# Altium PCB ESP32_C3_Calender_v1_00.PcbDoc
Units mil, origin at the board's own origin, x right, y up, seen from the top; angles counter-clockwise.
Board outline 2500 x 1692.91 mil, 2 copper layers (Top Layer, Bottom Layer), stack 65.792 mil thick; 16 components, 17 nets, 85 pads, 115 vias.
Unrouted connection lines stored in the file: 42.
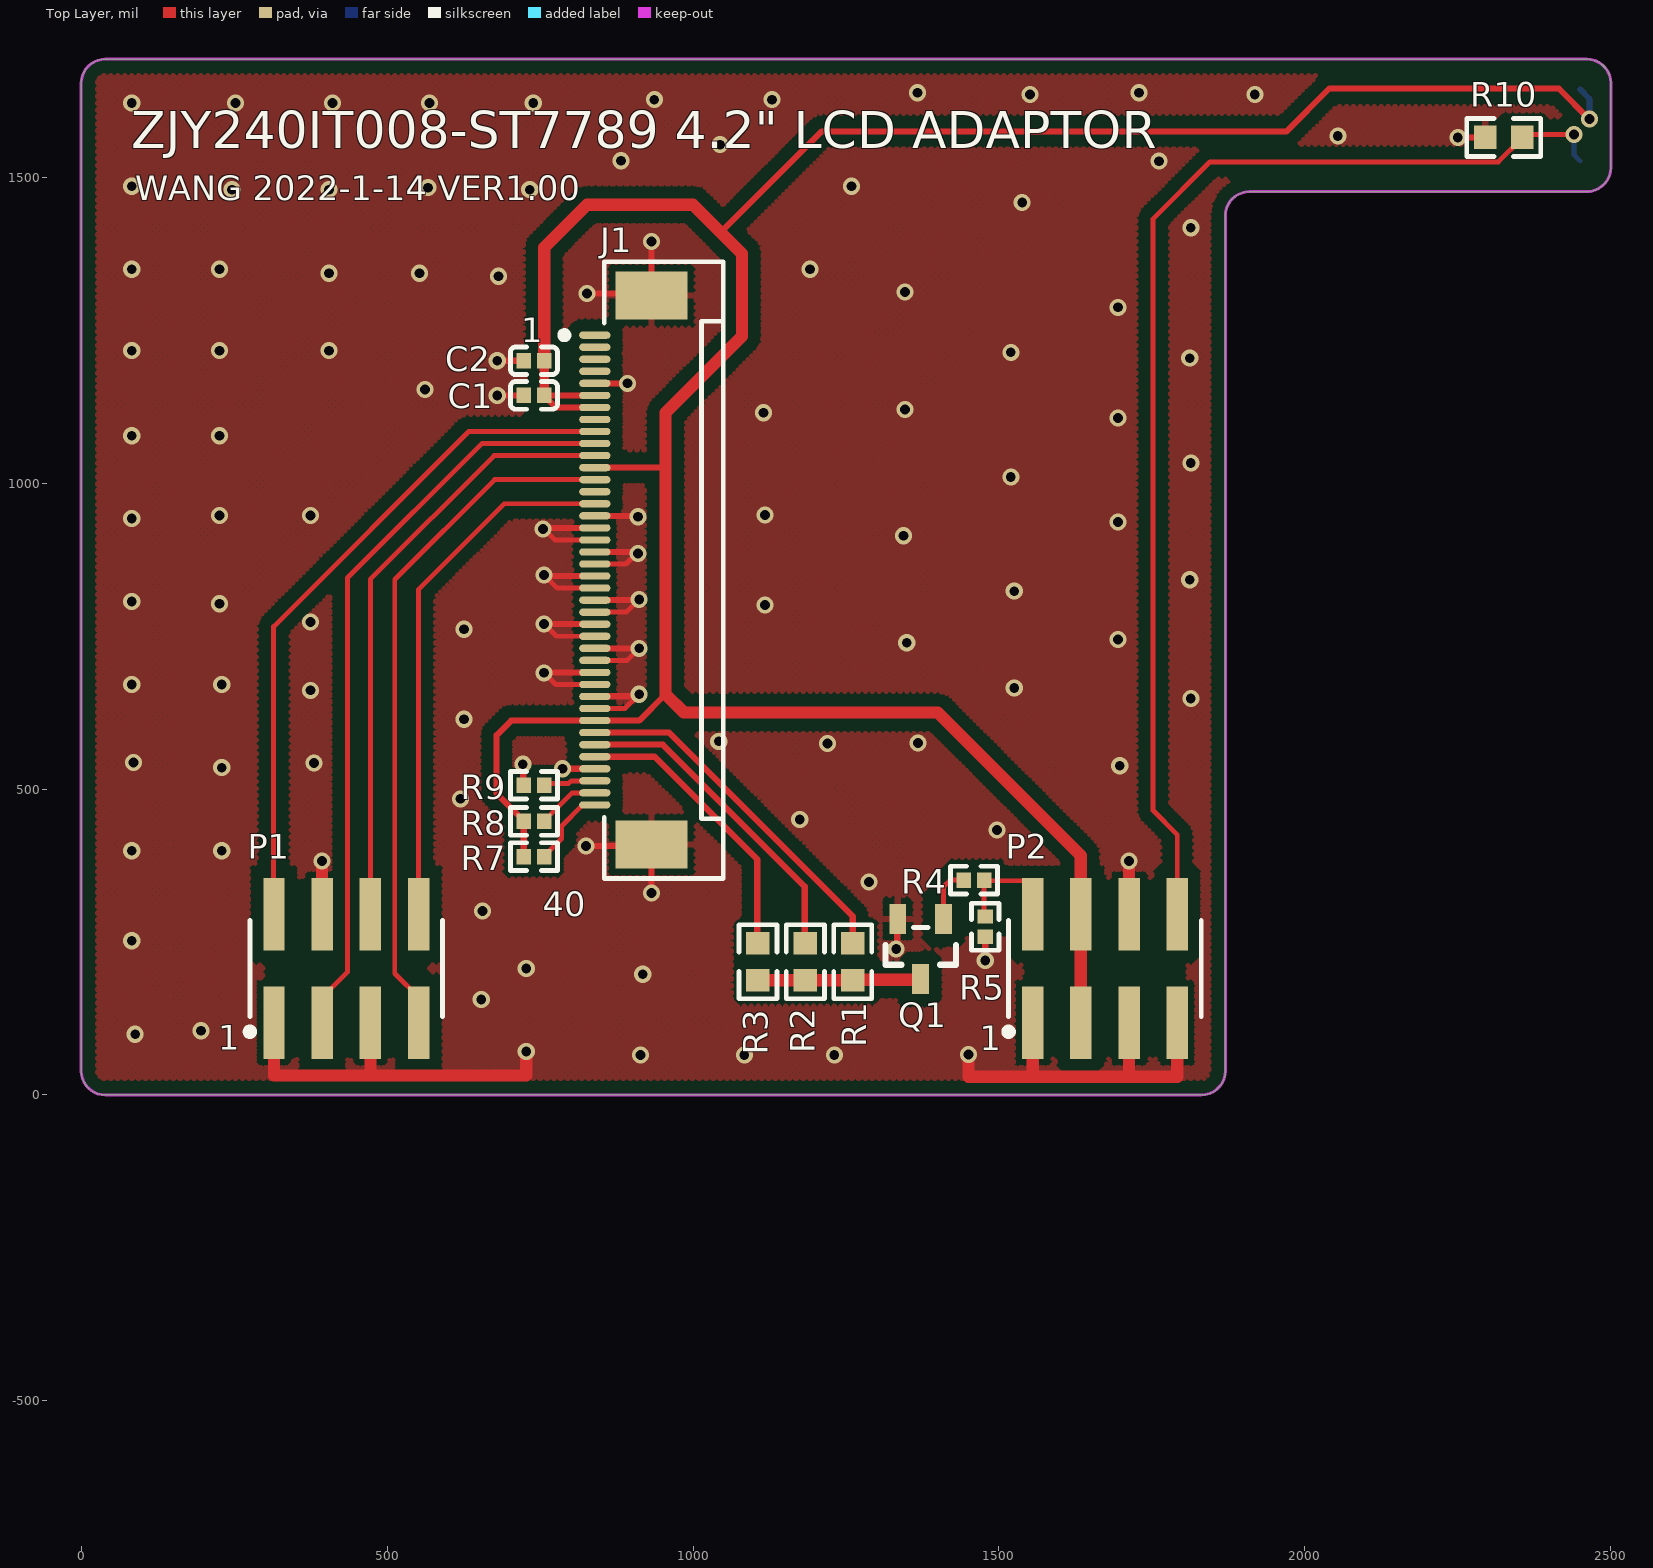
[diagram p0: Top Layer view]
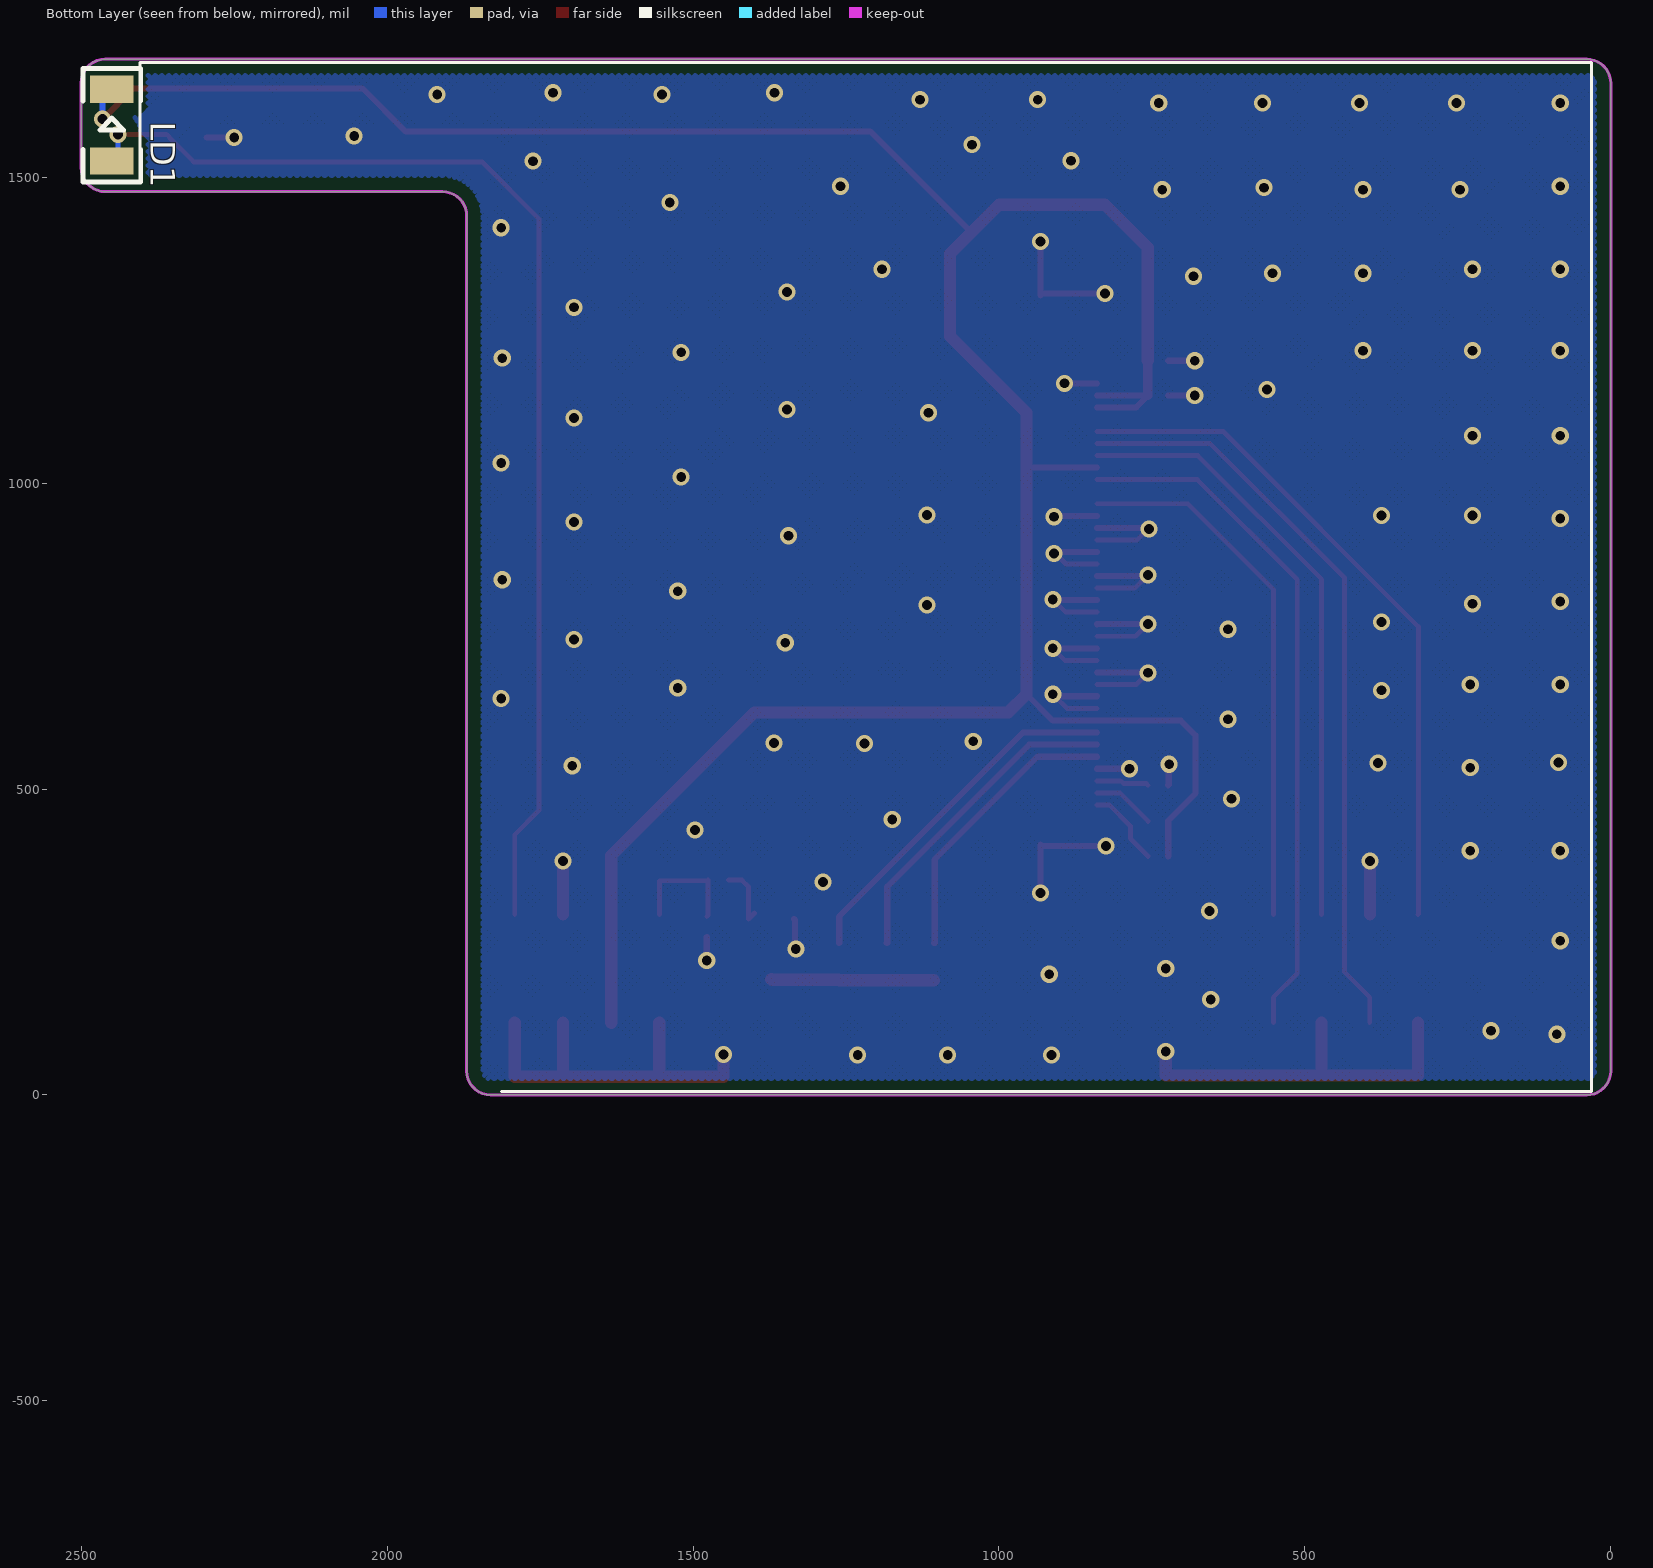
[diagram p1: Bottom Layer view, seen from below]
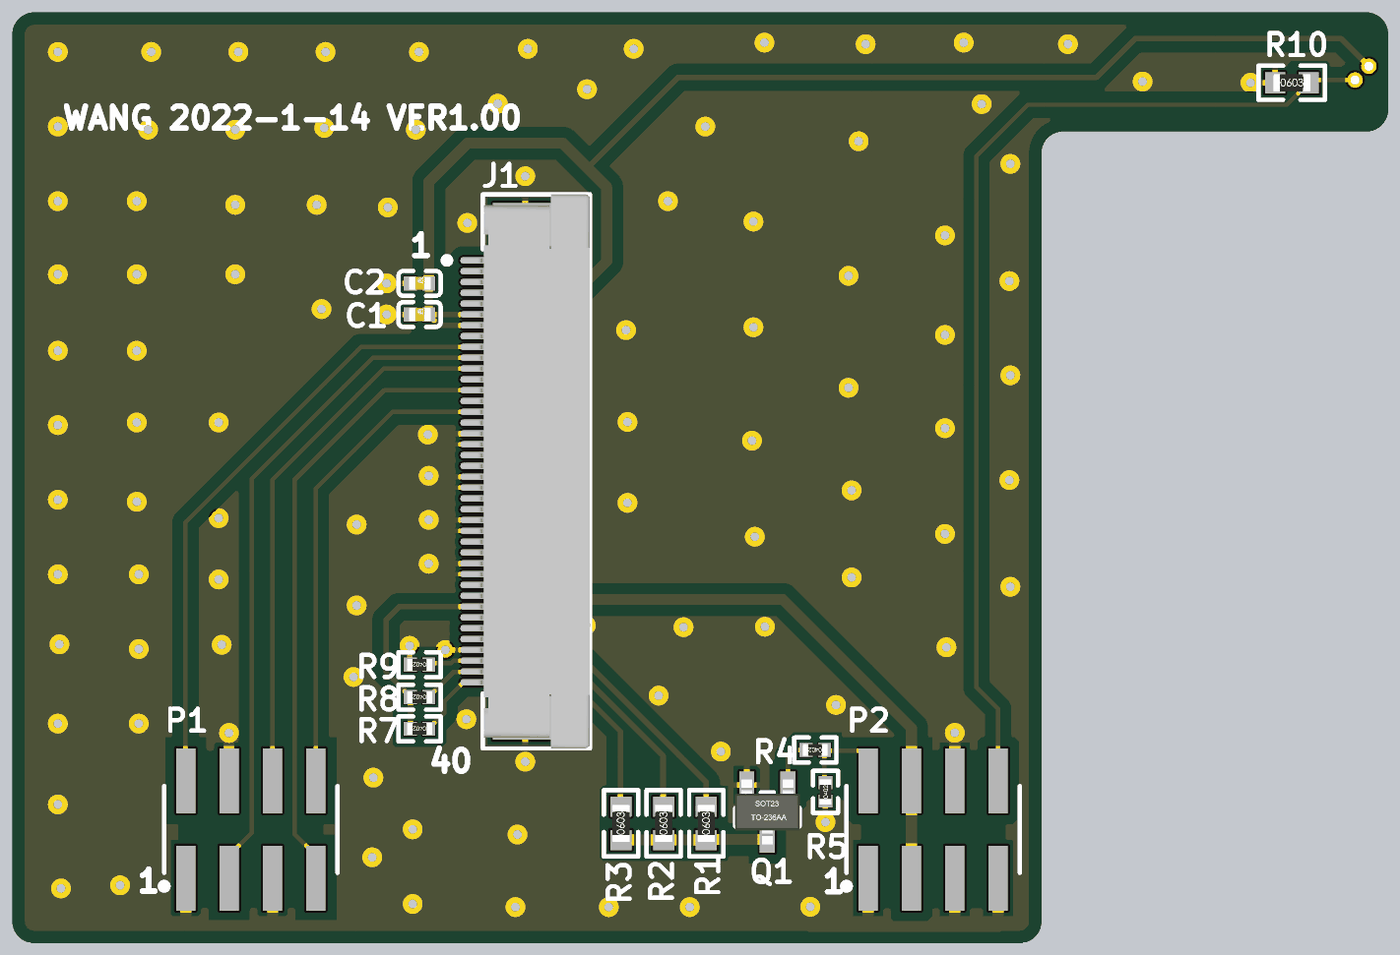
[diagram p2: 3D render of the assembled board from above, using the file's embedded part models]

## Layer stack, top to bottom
Top Solder: solder mask 0.4, Solder Resist, Dk 3.5
Top Layer: signal copper 1.4
Dielectric 1: dielectric 62.9921, FR-4, Dk 4.8
Bottom Layer: signal copper 1.4
Bottom Solder: solder mask 0.4, Solder Resist, Dk 3.5

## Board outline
0,39.37 ccw(c39.37,39.37) 39.37,0 1830.71,0 ccw(c1830.71,39.37) 1870.08,39.37 1870.08,1437.01 cw(c1909.45,1437.01) 1909.45,1476.38 2460.63,1476.38 ccw(c2460.63,1515.75) 2500,1515.75 2500,1653.54 ccw(c2460.63,1653.54) 2460.63,1692.91 39.37,1692.91 ccw(c39.37,1653.54) 0,1653.54

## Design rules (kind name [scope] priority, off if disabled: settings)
Clearance Clearance_3 [InNamedPolygon('GND_L02_P006') Or  InNamedPolygon('GND_L01_P004')] p1: gap=20 ignorepadtopadclearanceinfootprint=FALSE
Clearance Clearance_2 [InNamedPolygon('GND_L02_P006') Or  InNamedPolygon('GND_L01_P004')] p2: gap=10 ignorepadtopadclearanceinfootprint=FALSE except(0: Arc-Hole Track-Hole SMDPad-Hole THPad-Hole Via-Hole Fill-Hole Poly-Hole Region-Hole Text-Hole)
Clearance Clearance_1 [InNamedPolygon('GND_L01_P000') Or  InNamedPolygon('GND_BOTTOM')] p3: gap=15 ignorepadtopadclearanceinfootprint=FALSE
Clearance [All] p4: gap=6 ignorepadtopadclearanceinfootprint=FALSE
ComponentClearance [All] p1: gap=2 collisioncheckmode=3 verticalgap=0 showdistances=FALSE
HoleSize [All] p1: absolutevalues=TRUE maxlimit=200 minlimit=1 maxpercent=80.000 minpercent=20.000
MinimumSolderMaskSliver [All] p1: minsoldermaskwidth=0
PolygonConnect PolygonConnect_2 [InNet('GND') vs IsThruPin] p1: connectstyle=Direct reliefconductorwidth=10 reliefentries=4 polygonreliefangle="90 Angle" airgapwidth=10
PolygonConnect PolygonConnect_1 [IsVia] p2: connectstyle=Direct reliefconductorwidth=10 reliefentries=4 polygonreliefangle="90 Angle" airgapwidth=10
PolygonConnect [All] p3: connectstyle=Relief reliefconductorwidth=10 reliefentries=4 polygonreliefangle="90 Angle" airgapwidth=10
RoutingVias [All] p1: holewidth=16 width=28 viastyle="Through Hole" minholewidth=16 minwidth=28 maxholewidth=28 maxwidth=50
SilkToSilkClearance [All] p1: silktosilkclearance=0
SilkToSolderMaskClearance [IsPad] p1: minsilkscreentomaskgap=0 clearancetoexposedcopper=TRUE
SolderMaskExpansion [All] p1: expansion=4
Width [All] p1: maxlimit=30 minlimit=8 preferedwidth=10
25 further rules are at their usual default settings.

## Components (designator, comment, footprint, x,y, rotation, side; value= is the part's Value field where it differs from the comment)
C1 "4.7uF (475) 20% 10V" LC-0402_C 740,1143.43 r0 top
C2 "100nF (104) 10% 16V" LC-0402_C 740,1200 r0 top
J1 "FPC40 Socket" FPC40-P0.5-2 876.25,858 r90 top locked
LD1 "PTSMD026" LC-1206_DIODE 2450,1585 r90 bottom
P1 "Header 4X2" HDR2X4-P2-SMD 433.3,206.69 r0 top locked
P2 "Header 4X2" HDR2X4-P2-SMD 1673.23,206.69 r0 top locked
Q1 "SS8050 Y1" LC-SOT-23(SOT-23-3) 1372,238.49 r90 top
R1 "33Ω (33R0) ±1%" LC-0603_R 1261,217.81 r90 top
R2 "33Ω (33R0) ±1%" LC-0603_R 1183.5,217.81 r90 top
R3 "33Ω (33R0) ±1%" LC-0603_R 1106,217.81 r90 top
R4 "1KΩ (1001) ±1%" LC-0402_R 1459,351.16 r180 top
R5 "4.7KΩ (4701) ±1%" LC-0402_R 1477.57,275 r90 top
R7 "4.7KΩ (4701) ±1%" LC-0402_R 740,389.61 r180 top
R8 "4.7KΩ (4701) ±1%" LC-0402_R 740,447.24 r180 top
R9 "4.7KΩ (4701) ±1%" LC-0402_R 740,506.3 r180 top
R10 "3.9KΩ (3901) ±1%" LC-0603_R 2325,1565 r0 top

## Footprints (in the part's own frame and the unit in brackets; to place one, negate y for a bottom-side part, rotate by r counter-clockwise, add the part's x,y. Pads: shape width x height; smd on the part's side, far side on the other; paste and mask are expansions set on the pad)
FPC40-P0.5-2 [mm] "X05B20U40T"
  oval 0.3x1.3 smd: 1(9.75,0.934) 2(9.25,0.934) 3(8.75,0.934) 4(8.25,0.934) 5(7.75,0.934) 6(7.25,0.934) 7(6.75,0.934) 8(6.25,0.934) 9(5.75,0.934) 10(5.25,0.934) 11(4.75,0.934) 12(4.25,0.934) 13(3.75,0.934) 14(3.25,0.934) 15(2.75,0.934) 16(2.25,0.934) 17(1.75,0.934) 18(1.25,0.934) 19(0.75,0.934) 20(0.25,0.934) 21(-0.25,0.934) 22(-0.75,0.934) 23(-1.25,0.934) 24(-1.75,0.934) 25(-2.25,0.934) 26(-2.75,0.934) 27(-3.25,0.934) 28(-3.75,0.934) 29(-4.25,0.934) 30(-4.75,0.934) 31(-5.25,0.934) 32(-5.75,0.934) 33(-6.25,0.934) 34(-6.75,0.934) 35(-7.25,0.934) 36(-7.75,0.934) 37(-8.25,0.934) 38(-8.75,0.934) 39(-9.25,0.934) 40(-9.75,0.934)
  rect 2x3 smd: BK1(-11.4,-1.416) BK2(11.4,-1.416)
  silkscreen extent -12.8,-4.4 12.8,2.34, body extent -12.8,-4.4 12.8,1.57, height 2
HDR2X4-P2-SMD [mm]
  rect 0.89x3 smd: 1(-3,-2.25) 2(-3,2.25) 3(-1,-2.25) 4(-1,2.25) 5(1,-2.25) 6(1,2.25) 7(3,-2.25) 8(3,2.25)
  silkscreen extent -4.15,-2.77 4,2, body extent -4,-3.2 4,3.2, height 7.1
LC-0402_C [mm]
  rect 0.6x0.65 smd mask+0.051: 1(-0.425,0) 2(0.425,0)
  silkscreen extent -0.97,-0.58 0.97,0.58, body extent -0.48,-0.3 0.52,0.3, height 0.2
LC-0402_R [mm]
  rect 0.6x0.65 smd mask+0.051: 1(-0.425,0) 2(0.425,0)
  silkscreen extent -0.97,-0.58 0.97,0.58, body extent -0.57,-0.27 0.58,0.28, height 0.41
LC-0603_R [mm]
  rect 0.93x0.98 smd: 1(-0.77,0) 2(0.77,0)
  silkscreen extent -1.53,-0.79 1.54,0.79, body extent -0.85,-0.4 0.85,0.4, height 0.56
LC-1206_DIODE [mm]
  rect 1.13x1.8 smd: 1(-1.49,0) 2(1.49,0)
  silkscreen extent -2.36,-1.2 2.35,1.2, body extent -1.7,-0.86 1.65,0.87, height 0.85
LC-SOT-23(SOT-23-3) [mm]
  rect 1.25x0.7 smd: 1(1.25,-0.95) 2(1.25,0.95) 3(-1.25,0)
  silkscreen extent -0.65,-1.46 0.9,1.46, body extent -1.5,-1.5 1.5,1.5, height 1.3

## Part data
C1: library part "0402 4.7uF (475) 20% 10V", "贴片电容", Package=0402, SuppliersPartNumber=C23733
C2: library part "0402 100nF (104) 10% 16V", "贴片电容", Package=0402, SuppliersPartNumber=C1525
J1: library part FPC40
LD1: library part OPTTRANS, "NPN General Purpose Amplifier"
P1 P2: "Header, 4-Pin, Dual row"
Q1: library part "SOT-23 SS8050 Y1", "三极管", Package=SOT-23, SuppliersPartNumber=C2150
R1 R2 R3: library part "0603 33Ω (33R0) 1%", "贴片电阻", Package=0603, SuppliersPartNumber=C23140
R4: library part "0402 1KΩ (1001) 1%", "贴片电阻", Package=0402, SuppliersPartNumber=C11702
R5 R7 R8 R9: library part "0402 4.7KΩ (4701) 1%", "贴片电阻", Package=0402, SuppliersPartNumber=C25900
R10: library part "0603 3.9KΩ (3901) 1%", "贴片电阻", Package=0603, SuppliersPartNumber=C23018

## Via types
v1: diameter 28, hole 16, Top Layer to Bottom Layer, 115 vias

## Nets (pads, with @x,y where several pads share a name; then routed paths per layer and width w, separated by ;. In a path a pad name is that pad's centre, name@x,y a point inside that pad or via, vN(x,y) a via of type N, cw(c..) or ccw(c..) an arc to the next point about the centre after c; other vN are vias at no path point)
+3.3V: C1.2 C2.2 J1.6 J1.7 J1.12 J1.33 LD1.2 P2.3 P2.4 R7.2 R8.2 | length 4863.8
  Top Layer w10: R7.2 R8.2 723.27,448.23 678.94,492.56 678.94,588.26 702.61,611.94 J1.33 911.94,611.94 955,655 ; J1.12 953.94,1025.32 955,1024.26 ; J1.7 775.43,1123.75 756.73,1142.45 C1.2 J1.6 ; 1045,1410 1210,1575 1970,1575 2040,1645 2415,1645 v1(2465,1595)
  Top Layer w15: C1.2 C2.2
  Top Layer w20: C2.2 756.73,1385 826.73,1455 1000,1455 1045,1410 1080,1375 1080,1240 955,1115 955,1024.26 955,655 985,625 1400,625 1633.86,391.14 P2.4 P2.3
  Bottom Layer w10: LD1.2 2465,1628.66 v1(2465,1595)
ENV_LUX_ADC: LD1.1 P2.8 R10.2 | length 1946.6
  Top Layer w8: P2.8 1791.34,425.66 1752,465 1752,1432 1845,1525 2316.3,1525 2355.32,1564.02 R10.2 2360.32,1570 v1(2440,1570)
  Bottom Layer w8: v1(2440,1570) 2440,1536.34 LD1.1
GND: C1.1 C2.1 J1.5 J1.16 J1.17 J1.18 J1.19 J1.20 J1.21 J1.22 J1.23 J1.24 J1.25 J1.26 J1.27 J1.28 J1.29 J1.30 J1.31 J1.32 J1.37 J1.BK1 J1.BK2 P1.1 P1.4 P1.5 P2.1 P2.5 P2.6 P2.7 Q1.2 R5.1 R9.2 R10.1 | length 3556.9
  Top Layer w8: v1(755,925) 756.19,925 773.98,907.21 J1.18 ; v1(756.55,690) 775.56,670.99 J1.30 ; v1(756.55,770) 756.84,769.71 776.82,749.73 J1.26 ; v1(756.55,850) 758.05,848.5 778.08,828.47 J1.22 ; J1.32 888.56,631.62 v1@908.59,651.65 ; J1.28 892.3,710.36 v1(911.94,730) ; J1.24 891.04,789.1 911.07,809.13 v1(911.94,810) ; J1.20 890.39,867.84 907.82,885.27 v1@907.82,887.18
  Top Layer w10: P1.1@314.5,117.43 P1.1 ; P1.4@393.7,295.5 P1.4 ; v1(680,1143.43) C1.1 ; v1(680,1200) C2.1 ; v1(721.8,540.61) 722.53,539.88 722.53,507.03 R9.2 ; v1(755,925) 756.55,926.55 839.13,926.55 J1.17 ; v1(756.55,690) 756.89,690.34 839.14,690.34 J1.29 ; v1@756.84,769.71 839.19,769.71 J1.25 ; v1@758.05,848.5 839.13,848.5 J1.21 ; v1(786.8,533.2) J1.37 ; v1(825,407.18) 930,407.18 J1.BK1 v1(932,330) ; v1(826.73,1310) 928.82,1310 J1.BK2 v1(932,1395) ; J1.31 839.83,651.65 v1@908.59,651.65 ; J1.23 839.83,809.13 v1@911.07,809.13 ; J1.19 839.83,887.18 v1@907.82,887.18 ; J1.16 839.83,946.24 908.76,946.24 v1(910,945) ; J1.5 v1(893.12,1163.12) ; J1.27 v1@911.91,730.02 ; v1(1332,238.49) 1333.3,239.79 1333.3,286.41 Q1.2 ; v1(1477.57,220) R5.1 ; P2.7 P2.7@1795,114.45 ; v1(2250,1565) R10.1
  Top Layer w20: P1.1 315.19,32 472.89,32 ; P1.4@393.7,295.5 v1(393.7,382.22) ; P1.5 472.89,118.11 472.89,32 ; v1(727.45,71.09) 727.45,32 472.89,32 ; v1(1450,66) 1450,30 1555.12,30 ; P2.1 1555.12,30 ; P2.5 1712.6,30 ; P2.6 v1(1712.6,382.4) ; P2.7 1791.34,30 1712.6,30 ; 1555.12,30 1712.6,30
  other v1: 914.13,65.44 1083.83,65.44 1230.91,65.44 88.23,99.38 195.71,105.03 653.91,155.95 917.91,197.42 727.45,206.86 82.57,252.11 656,300.94 1287.48,348.28 82.57,399.19 229.65,399.19 1496.78,433.13 1174.34,450.1 619.97,484.04 229.65,534.96 1697.35,538.04 85.44,543.4 380.4,542.6 1219.6,574.55 1367.55,575.43 1042.02,578 625.63,614.15 1813.57,648.09 911.94,655 374.75,661.38 1525.07,665.06 82.57,670.72 229.65,670.72 1349.18,739.13 1694.77,744.26 625.63,761.23 374.75,773 1117.78,800.83 225.98,802.82 82.57,806.48 1525.07,823.45 1811.79,842.21 910,885 1344.05,913.96 1694.78,936.59 82.57,942.25 225.98,947 374.75,947 1117.78,947.91 1519.41,1010.13 1813.57,1032.76 82.57,1077.52 225.98,1077.52 1694.77,1106.3 1115.16,1115 1346.64,1120.2 561.69,1153.26 1811.79,1204.24 1519.41,1213.78 82.57,1216.54 225.98,1216.54 405.01,1216.54 1694.77,1287.32 1346.64,1312.54 682.2,1338.23 405.01,1342.95 553.03,1342.95 82.57,1349.54 225.98,1349.54 1191.32,1349.54 1813.57,1417.43 1537.92,1458.56 246.62,1479.65 405.01,1479.65 733.11,1479.65 566.65,1482.9 82.57,1485.31 1259.2,1485.31 1761.35,1526.21 882.15,1526.87 1044.24,1553.19 2053.85,1567.2 82.57,1621.07 252.28,1621.07 410.67,1621.07 569.06,1621.07 738.77,1621.07 936.76,1626.73 1129.09,1626.73 1550.53,1635.21 1918.21,1635.21 1366.68,1638.04 1728.72,1638.04
IM0: J1.38 R9.1 | length 85.7
  Top Layer w8: R9.1 759.63,509.2 796.74,509.2 801.06,513.51 J1.38
IM1: J1.39 R8.1 | length 102.6
  Top Layer w8: R8.1 756.73,448.23 801.89,493.39 839.04,493.39 J1.39
IM2: J1.40 R7.1 | length 130.3
  Top Layer w8: R7.1 756.73,390.59 785,418.86 785,439.35 819.8,474.14 J1.40
LCD_BK: P2.2 R4.1 R5.2 | length 194.5
  Top Layer w8: R4.1 R4.1@1475.73,350.18 ; R5.2 1475.73,293.57 R4.1@1475.73,350.18 ; P2.2 1555.12,350.18 R4.1@1475.73,350.18
LCD_CSn: J1.9 P1.2 | length 1127.6
  Top Layer w8: P1.2 314.5,295.96 314.5,765.5 633.38,1084.38 J1.9
LCD_DC: J1.11 P1.6 | length 998
  Top Layer w8: P1.6 472.67,842.67 675.01,1045.01 J1.11
LCD_RESETn: J1.15 P1.8 | length 877.1
  Top Layer w8: P1.8 551.41,826.41 691.27,966.27 J1.15
LCD_SCL: J1.10 P1.3 | length 1239.4
  Top Layer w8: P1.3 393.93,159.65 435,200.72 435,845 654.69,1064.69 J1.10
LCD_SDA: J1.13 P1.7 | length 1135.1
  Top Layer w8: P1.7 551.41,159.65 512.49,198.56 512.49,842.49 675.64,1005.64 J1.13
LED_K1: J1.34 R1.2 | length 589.8
  Top Layer w10: J1.34 960.75,592.25 1261,292 R1.2
LED_K2: J1.35 R2.2 | length 532.5
  Top Layer w10: J1.35 950.43,572.57 1182.52,340.48 1182.52,248.12 R2.2
LED_K3: J1.36 R3.2 | length 472.9
  Top Layer w10: J1.36 937.12,552.88 1105.02,384.98 1105.02,248.12 R3.2
NetQ1_1: Q1.1 R4.2 | length 103.8
  Top Layer w8: Q1.1@1399.62,297.49 Q1.1 1409.4,340.4 1420.16,351.16 R4.2
NetQ1_3: Q1.3 R1.1 R2.1 R3.1 | length 266.7
  Top Layer w20: R3.1 R1.1 1261.89,188.39 1371.11,188.39 Q1.3
pads on no net: J1.1 J1.2 J1.3 J1.4 J1.8 J1.14

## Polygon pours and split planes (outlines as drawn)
GND on Top Layer "GND_L01_P004" (hatched 45Degree grid 8 track 8, remove dead copper, pour order 4): 0,0 2500,0 2500,1692.91 0,1692.91
GND on Bottom Layer "GND_L02_P006" (hatched 45Degree grid 8 track 8, remove dead copper, pour order 6): 0,0 2500,0 2500,1692.91 0,1692.91

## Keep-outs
Keep-Out Layer:
  lines w5: 0,39.37 ccw(c39.37,39.37) 39.37,0 1830.71,0 ccw(c1830.71,39.37) 1870.08,39.37 1870.08,1261.42 1870.08,1437.01 cw(c1909.45,1437.01) 1909.45,1476.38 2460.63,1476.38 ccw(c2460.63,1515.75) 2500,1515.75 2500,1653.54 ccw(c2460.63,1653.54) 2460.63,1692.91 39.37,1692.91 ccw(c39.37,1653.54) 0,1653.54 0,39.37

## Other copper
Top Layer:
  pour cut-out: 877.92,1259 877.92,459 806,459 806,1259
  pour cut-out: 1538,59 1809,59 1809,355 1538,355
  pour cut-out: 297.53,353.94 297.53,59.78 569.06,59.78 569.06,353.94
  region: 844.94,529.13
  region: 1264.37,-679.41

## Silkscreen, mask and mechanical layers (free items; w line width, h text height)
Top Overlay:
  text "ZJY240IT008-ST7789 4.2\" LCD ADAPTOR" at 82,1547 h60
  text "WANG 2022-1-14 VER1.00" at 88,1462 h40
  text "1" at 719,1230 h40
  text "40" at 754,292 h40
  text "1" at 224,74 h40
  text "1" at 1469,73 h40
Bottom Overlay:
  lines w5: 1812.97,5.51 31.5,5.51 31.5,1687.4 2403.94,1687.4 2403.94,1498.6
Mechanical 1:
  lines w5: 0,39.37 ccw(c39.37,39.37) 39.37,0 1830.71,0 ccw(c1830.71,39.37) 1870.08,39.37 1870.08,1261.42 1870.08,1437.01 cw(c1909.45,1437.01) 1909.45,1476.38 2460.63,1476.38 ccw(c2460.63,1515.75) 2500,1515.75 2500,1653.54 ccw(c2460.63,1653.54) 2460.63,1692.91 39.37,1692.91 ccw(c39.37,1653.54) 0,1653.54 0,39.37
Mechanical 15:
  drawing of 747 lines, arcs and shapes, not listed
Mechanical 16:
  drawing of 805 lines, arcs and shapes, not listed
